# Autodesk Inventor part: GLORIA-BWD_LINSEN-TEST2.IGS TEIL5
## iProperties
Created: 2005-04
Part Number: GLORIA-BWD_LINSEN-TEST2.IGS TEIL5
Document SubType Name: Modeling
Designer: Nordmeyer
Manufacturer: Standard
Standards Organization: Custom
Author: Nordmeyer
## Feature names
1. Erst1
